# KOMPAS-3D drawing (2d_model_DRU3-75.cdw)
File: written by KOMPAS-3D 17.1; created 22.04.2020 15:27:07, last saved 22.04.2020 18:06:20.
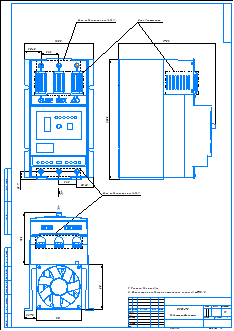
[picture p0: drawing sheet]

Sheet 1: A2, portrait

Title block, sheet 1: name: DRU3-75 / Габаритный чертеж; sheets: 1; sheet format: A2; stored path: E:\Марк\DRU3\DRU3-XX\2d_model_DRU3-100.cdw

Views: Вид по стрелке 3
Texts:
  Пользователь Windows
  HHT100ЙўИИЖч_40A
  100AµзБ¦µчХыЖчЙПёЗ(2014.5.12РЮёД)
  µзБ¦µчХыЖчРэЕҐ
Dimensions and other numbers on the sheet: 1:1; 1; 100AµзБ¦µчХыЖчєуЧщ; 100AµзБ¦µчХыЖчµЧЧщ; 100AµзБ¦µчХыЖчЅУПЯЧщ; 100AµзБ¦µчХыЖчЅУПЯЖ¬; 80·з»ъ; 100AµзБ¦µчХыЖч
